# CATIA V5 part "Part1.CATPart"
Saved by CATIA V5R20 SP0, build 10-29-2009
Part number: Part1
Bounding box of the stored display mesh (mm): x 0 to 50, y 0 to 260, z 0 to 100
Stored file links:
  C:\Users\Ehsan Fathi\Desktop\Part1.CATPart
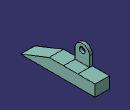
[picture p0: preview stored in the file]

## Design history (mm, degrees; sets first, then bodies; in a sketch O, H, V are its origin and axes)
Body1 (main body)
  Sketch1 on yz-plane, origin (0, 0, 0), H (0, 1, 0), V (0, 0, 1)
    line L1 (0, 0) -> (100, 40)
    line L2 (100, 40) -> (150, 40)
    line L3 (200, 0) -> (0, 0)
    line L4 (200, 40) -> (200, 100)
    line L5 (200, 100) -> (150, 100)
    line L6 (150, 100) -> (150, 40)
    line L7 (150, 40) -> (200, 40)
    circle A1 centre (175, 80) radius 10
    point P7 (175, 80)
    line L8 (200, 40) -> (260, 40)
    line L9 (260, 40) -> (260, 0)
    line L10 (260, 0) -> (200, 0)
    distance P7 V = 175
    radius A1 = 10
    horizontal: L2 H, L3 H, L5 H, L7 H, L8 H, L10 H
    vertical: L4 V, L6 V, L9 V
    coincidence: L2 L7
  MultiPad1: profile Sketch1, domains (length 0; length 10; length 50)
  TritangentFillet1: Face1 face of MultiPad1 from Sketch1.L4, RemoveFace face of MultiPad1 from Sketch1.L5, Face2 face of MultiPad1 from Sketch1.L6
